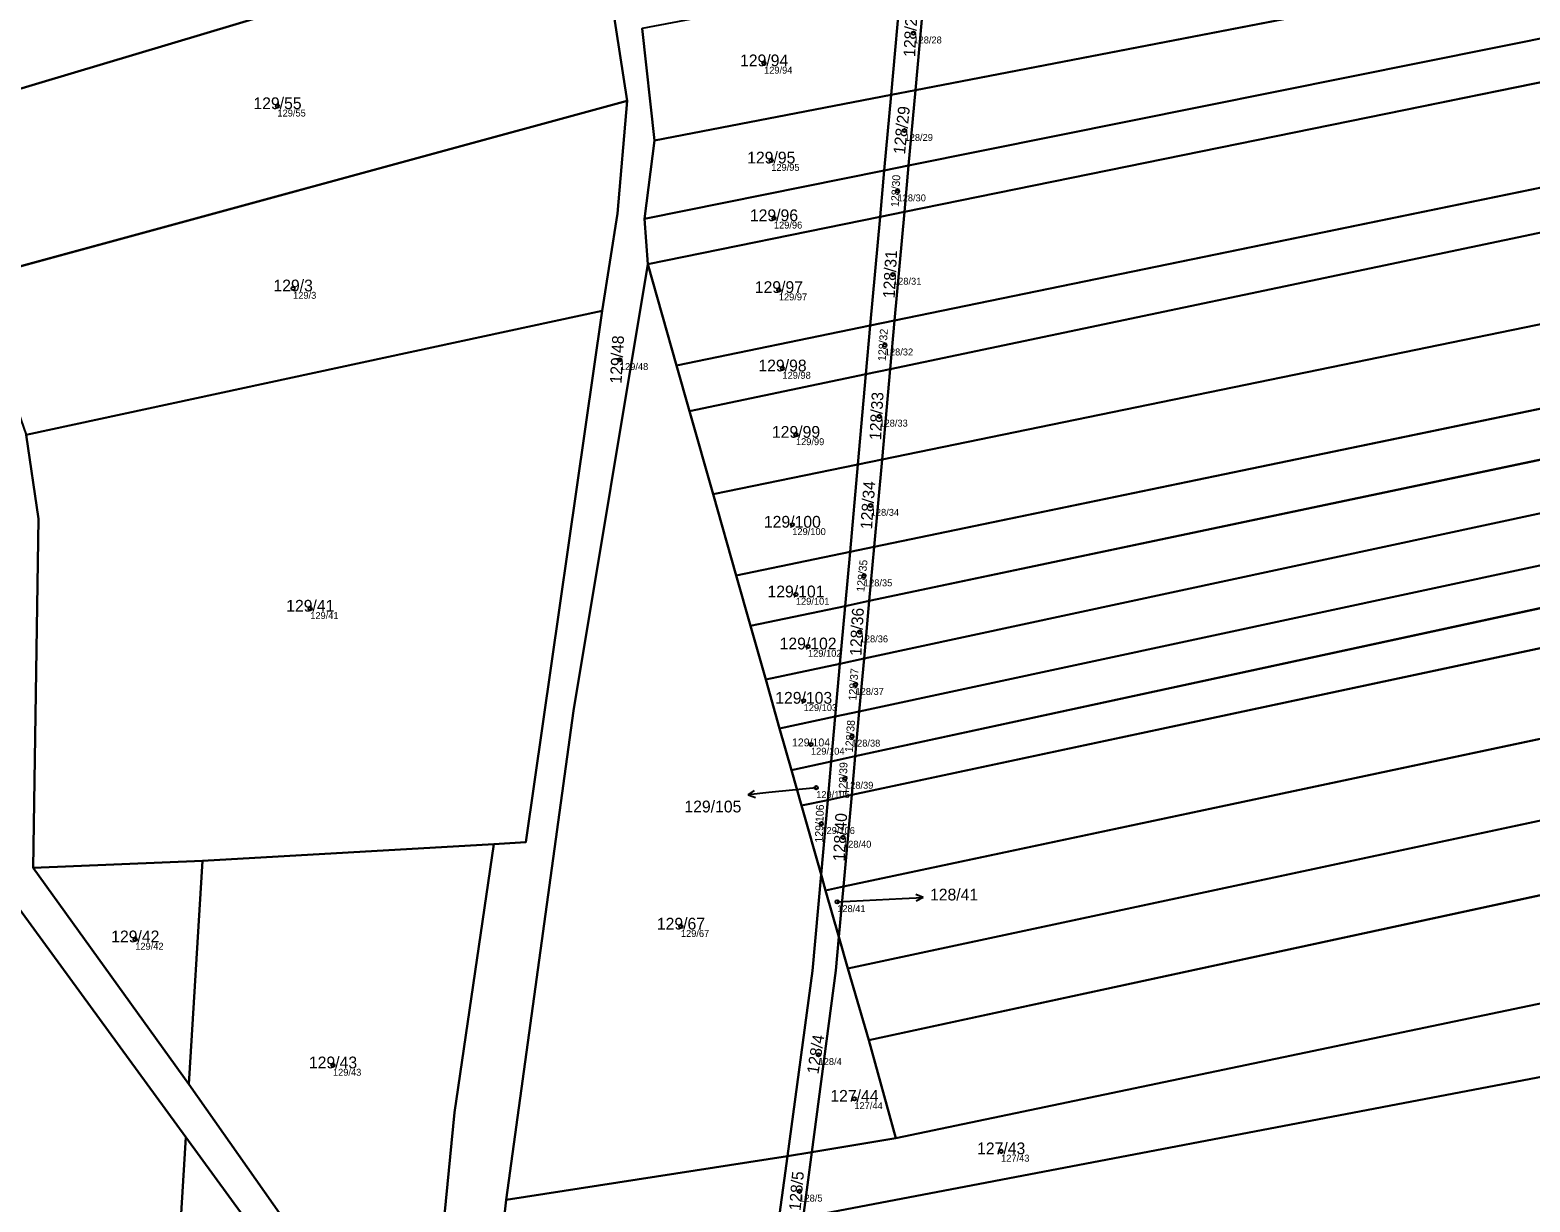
# Model space of a CAD drawing. Extents: x -603967 to -594699, y -1179315 to -1165625.
# Drawn here: x -597898.4 to -597682, y -1173367 to -1173197.8 of the extents above; entities that cross this region are included whole.
import ezdxf

# ---------------------------------------------------------------- set-up
doc = ezdxf.new("R2010")
doc.units = 0
for name, color, linetype in [('Definiční body', 7, 'Continuous'), ('Hranice parcel', 7, 'Continuous'), ('Parcelní čísla', 7, 'Continuous'), ('Polygon parcely', 7, 'Continuous'), ('Pop  PČ popisy', 7, 'Continuous')]:
    doc.layers.add(name, color=color, linetype=linetype)

msp = doc.modelspace()

# ---------------------------------------------------------------- linework, layer by layer
at = {"layer": 'Definiční body'}
for centre in [(-597770.92, -1173198.27994), (-597792.47, -1173202.63994), (-597862.68, -1173208.82994), (-597772.2, -1173212.34994), (-597791.44, -1173216.66994), (-597773.21, -1173221.07994), (-597791.05, -1173224.99994), (-597773.87, -1173233.10994), (-597860.42, -1173235.13994), (-597790.34, -1173235.36994), (-597775.05, -1173243.31994), (-597813.27, -1173245.42994), (-597789.82, -1173246.68994), (-597775.83, -1173253.58994), (-597787.87, -1173256.26994), (-597777.08, -1173266.46994), (-597788.4, -1173269.24994), (-597778.06, -1173276.64994), (-597787.88, -1173279.30994), (-597857.95, -1173281.36994), (-597778.67, -1173284.73994), (-597786.13, -1173286.81994), (-597779.28, -1173292.32994), (-597786.76, -1173294.65994), (-597785.7, -1173300.95994), (-597779.79, -1173299.78994), (-597784.95, -1173307.20994), (-597780.79, -1173305.86994), (-597784.2, -1173312.39994), (-597781.08, -1173314.37994), (-597781.92, -1173323.67994), (-597804.47, -1173327.25994), (-597883.2, -1173329.10994), (-597784.61, -1173345.75994), (-597854.67, -1173347.29994), (-597779.44, -1173352.11994), (-597758.27, -1173359.69994), (-597787.38, -1173365.46994)]:
    msp.add_circle(centre, 0.25, dxfattribs=at)
at = {"layer": 'Hranice parcel'}
for p, q in [((-597770.63, -1173206.5), (-597579.29, -1173169.58)), ((-597771.62, -1173217.4), (-597581.1, -1173179.02)), ((-597916.3, -1173211.25), (-597816.35, -1173181.29)), ((-597816.35, -1173181.29), (-597812.23, -1173208.04)), ((-597772.22, -1173224.08), (-597582.31, -1173185.32)), ((-597772.65, -1173190.5), (-597774.15, -1173207.18)), ((-597769.12, -1173189.83), (-597770.63, -1173206.5)), ((-597808.28, -1173213.76), (-597810.05, -1173197.62)), ((-597773.64, -1173239.78), (-597585.85, -1173201.13)), ((-597812.23, -1173208.04), (-597906.75, -1173233.85)), ((-597808.28, -1173213.76), (-597774.15, -1173207.18)), ((-597774.15, -1173207.18), (-597775.13, -1173218.11)), ((-597774.27, -1173246.79), (-597587.4, -1173207.52)), ((-597774.15, -1173207.18), (-597770.63, -1173206.5)), ((-597770.63, -1173206.5), (-597771.62, -1173217.4)), ((-597809.7, -1173225.08), (-597808.28, -1173213.76)), ((-597775.45, -1173259.82), (-597560.35, -1173215.6)), ((-597809.7, -1173225.08), (-597775.13, -1173218.11)), ((-597775.13, -1173218.11), (-597775.73, -1173224.8)), ((-597775.13, -1173218.11), (-597771.62, -1173217.4)), ((-597771.62, -1173217.4), (-597772.22, -1173224.08)), ((-597809.24, -1173231.64), (-597809.7, -1173225.08)), ((-597809.24, -1173231.64), (-597775.73, -1173224.8)), ((-597775.73, -1173224.8), (-597777.14, -1173240.5)), ((-597775.73, -1173224.8), (-597772.22, -1173224.08)), ((-597772.22, -1173224.08), (-597773.64, -1173239.78)), ((-597776.59, -1173272.46), (-597564.2, -1173228.37)), ((-597805.1, -1173246.25), (-597809.24, -1173231.64)), ((-597777.3, -1173280.25), (-597566.44, -1173235.83)), ((-597898.92, -1173256.25), (-597815.82, -1173238.39)), ((-597805.1, -1173246.25), (-597777.14, -1173240.5)), ((-597777.14, -1173240.5), (-597777.77, -1173247.52)), ((-597777.14, -1173240.5), (-597773.64, -1173239.78)), ((-597773.64, -1173239.78), (-597774.27, -1173246.79)), ((-597778.05, -1173288.56), (-597567.95, -1173243.42)), ((-597803.22, -1173252.87), (-597805.1, -1173246.25)), ((-597777.77, -1173247.52), (-597774.27, -1173246.79)), ((-597774.27, -1173246.79), (-597775.45, -1173259.82)), ((-597803.22, -1173252.87), (-597777.77, -1173247.52)), ((-597777.77, -1173247.52), (-597778.94, -1173260.54)), ((-597778.74, -1173296.2), (-597567.76, -1173250.91)), ((-597799.83, -1173264.83), (-597803.22, -1173252.87)), ((-597779.33, -1173302.68), (-597567.61, -1173256.87)), ((-597778.94, -1173260.54), (-597775.45, -1173259.82)), ((-597775.45, -1173259.82), (-597776.59, -1173272.46)), ((-597799.83, -1173264.83), (-597778.94, -1173260.54)), ((-597778.94, -1173260.54), (-597780.07, -1173273.18)), ((-597779.83, -1173308.25), (-597569.75, -1173263.44)), ((-597796.49, -1173276.59), (-597799.83, -1173264.83)), ((-597780.07, -1173273.18), (-597776.59, -1173272.46)), ((-597776.59, -1173272.46), (-597777.3, -1173280.25)), ((-597796.49, -1173276.59), (-597780.07, -1173273.18)), ((-597780.07, -1173273.18), (-597780.77, -1173280.98)), ((-597794.43, -1173283.86), (-597796.49, -1173276.59)), ((-597781.03, -1173321.48), (-597574.37, -1173277.63)), ((-597794.43, -1173283.86), (-597780.77, -1173280.98)), ((-597780.77, -1173280.98), (-597781.52, -1173289.31)), ((-597780.77, -1173280.98), (-597777.3, -1173280.25)), ((-597777.3, -1173280.25), (-597778.05, -1173288.56)), ((-597792.23, -1173291.61), (-597794.43, -1173283.86)), ((-597792.23, -1173291.61), (-597781.52, -1173289.31)), ((-597781.52, -1173289.31), (-597782.21, -1173296.94)), ((-597781.52, -1173289.31), (-597778.05, -1173288.56)), ((-597778.05, -1173288.56), (-597778.74, -1173296.2)), ((-597790.23, -1173298.66), (-597792.23, -1173291.61)), ((-597780.39, -1173333.33), (-597580.04, -1173290.5)), ((-597782.21, -1173296.94), (-597778.74, -1173296.2)), ((-597778.74, -1173296.2), (-597779.33, -1173302.68)), ((-597790.23, -1173298.66), (-597782.21, -1173296.94)), ((-597788.52, -1173304.67), (-597790.23, -1173298.66)), ((-597782.21, -1173296.94), (-597782.79, -1173303.43)), ((-597782.79, -1173303.43), (-597779.33, -1173302.68)), ((-597779.33, -1173302.68), (-597779.83, -1173308.25)), ((-597777.35, -1173343.67), (-597583.89, -1173301.84)), ((-597788.52, -1173304.67), (-597782.79, -1173303.43)), ((-597787.07, -1173309.8), (-597788.52, -1173304.67)), ((-597782.79, -1173303.43), (-597783.29, -1173308.99)), ((-597787.07, -1173309.8), (-597783.29, -1173308.99)), ((-597784.25, -1173319.72), (-597787.07, -1173309.8)), ((-597783.29, -1173308.99), (-597784.25, -1173319.72)), ((-597783.29, -1173308.99), (-597779.83, -1173308.25)), ((-597779.83, -1173308.25), (-597781.03, -1173321.48)), ((-597873.51, -1173317.76), (-597831.46, -1173315.35)), ((-597897.92, -1173318.78), (-597873.51, -1173317.76)), ((-597875.45, -1173349.99), (-597873.51, -1173317.76)), ((-597875.45, -1173349.99), (-597897.92, -1173318.78)), ((-597783.6, -1173322.03), (-597784.25, -1173319.72)), ((-597783.6, -1173322.03), (-597781.03, -1173321.48)), ((-597781.69, -1173328.74), (-597783.6, -1173322.03)), ((-597781.03, -1173321.48), (-597781.69, -1173328.74)), ((-597875.91, -1173357.65), (-597900.79, -1173323.49)), ((-597780.39, -1173333.33), (-597781.69, -1173328.74)), ((-597777.35, -1173343.67), (-597780.39, -1173333.33)), ((-597678.84, -1173338.04), (-597773.44, -1173357.81)), ((-597773.44, -1173357.81), (-597777.35, -1173343.67)), ((-597675.78, -1173348.07), (-597786.85, -1173369.25)), ((-597841.47, -1173398.41), (-597875.45, -1173349.99)), ((-597878.71, -1173404.2), (-597875.91, -1173357.65)), ((-597842.82, -1173403.09), (-597875.91, -1173357.65)), ((-597773.44, -1173357.81), (-597785.6, -1173359.83)), ((-597829.68, -1173366.71), (-597789.1, -1173360.41)), ((-597789.1, -1173360.41), (-597790.38, -1173369.9)), ((-597789.1, -1173360.41), (-597785.6, -1173359.83)), ((-597785.6, -1173359.83), (-597786.85, -1173369.25)), ((-597830.89, -1173377.41), (-597829.68, -1173366.71))]:
    msp.add_line(p, q, dxfattribs=at)
for points in [[(-597815.82, -1173238.39), (-597813.63, -1173224.32), (-597812.23, -1173208.04)], [(-597829.68, -1173366.71), (-597819.97, -1173296.09), (-597809.24, -1173231.64)], [(-597831.46, -1173315.35), (-597826.83, -1173315.09), (-597815.82, -1173238.39)], [(-597897.92, -1173318.78), (-597897.17, -1173268.39), (-597898.92, -1173256.25)], [(-597841.47, -1173398.41), (-597837.14, -1173354.1), (-597831.46, -1173315.35)], [(-597784.25, -1173319.72), (-597785.5, -1173333.66), (-597789.1, -1173360.41)], [(-597781.69, -1173328.74), (-597782.13, -1173333.58), (-597785.6, -1173359.83)]]:
    msp.add_lwpolyline(points, dxfattribs=at)
at = {"layer": 'Polygon parcely'}
for points in [[(-597868.05, -1172978.19), (-597856.03, -1173026.84), (-597831.11, -1173111.5), (-597822.95, -1173145.57), (-597822.21, -1173148.7), (-597816.35, -1173181.29), (-597812.23, -1173208.04), (-597813.63, -1173224.32), (-597815.82, -1173238.39), (-597826.83, -1173315.09), (-597831.46, -1173315.35), (-597837.14, -1173354.1), (-597841.47, -1173398.41)], [(-597830.89, -1173377.41), (-597829.68, -1173366.71), (-597819.97, -1173296.09), (-597809.24, -1173231.64), (-597809.7, -1173225.08), (-597808.28, -1173213.76), (-597810.05, -1173197.62)], [(-597841.47, -1173398.41), (-597875.45, -1173349.99), (-597897.92, -1173318.78), (-597897.17, -1173268.39), (-597898.92, -1173256.25)], [(-597900.79, -1173323.49), (-597875.91, -1173357.65), (-597842.82, -1173403.09)]]:
    msp.add_lwpolyline(points, dxfattribs=at)
for points in [[(-597816.35, -1173181.29), (-597822.21, -1173148.7), (-597922.8, -1173195.87), (-597916.3, -1173211.25)], [(-597578.94, -1173167.78), (-597576.49, -1173155.03), (-597576.38, -1173153.11), (-597769.12, -1173189.83), (-597770.63, -1173206.5), (-597579.29, -1173169.58)], [(-597581.1, -1173179.02), (-597579.29, -1173169.58), (-597770.63, -1173206.5), (-597771.62, -1173217.4)], [(-597582.31, -1173185.32), (-597581.1, -1173179.02), (-597771.62, -1173217.4), (-597772.22, -1173224.08)], [(-597906.75, -1173233.85), (-597812.23, -1173208.04), (-597816.35, -1173181.29), (-597916.3, -1173211.25)], [(-597772.22, -1173224.08), (-597773.64, -1173239.78), (-597585.85, -1173201.13), (-597583.42, -1173191.09), (-597582.31, -1173185.32)], [(-597774.15, -1173207.18), (-597772.65, -1173190.5), (-597810.05, -1173197.62), (-597808.28, -1173213.76)], [(-597770.63, -1173206.5), (-597769.12, -1173189.83), (-597772.65, -1173190.5), (-597774.15, -1173207.18)], [(-597773.64, -1173239.78), (-597774.27, -1173246.79), (-597587.4, -1173207.52), (-597585.85, -1173201.13)], [(-597558.84, -1173204.24), (-597587.4, -1173207.52), (-597774.27, -1173246.79), (-597775.45, -1173259.82), (-597560.35, -1173215.6)], [(-597898.92, -1173256.25), (-597815.82, -1173238.39), (-597813.63, -1173224.32), (-597812.23, -1173208.04), (-597906.75, -1173233.85)], [(-597775.13, -1173218.11), (-597774.15, -1173207.18), (-597808.28, -1173213.76), (-597809.7, -1173225.08)], [(-597774.15, -1173207.18), (-597775.13, -1173218.11), (-597771.62, -1173217.4), (-597770.63, -1173206.5)], [(-597564.2, -1173228.37), (-597560.35, -1173215.6), (-597775.45, -1173259.82), (-597776.59, -1173272.46)], [(-597775.73, -1173224.8), (-597775.13, -1173218.11), (-597809.7, -1173225.08), (-597809.24, -1173231.64)], [(-597772.22, -1173224.08), (-597771.62, -1173217.4), (-597775.13, -1173218.11), (-597775.73, -1173224.8)], [(-597777.14, -1173240.5), (-597775.73, -1173224.8), (-597809.24, -1173231.64), (-597805.1, -1173246.25)], [(-597773.64, -1173239.78), (-597772.22, -1173224.08), (-597775.73, -1173224.8), (-597777.14, -1173240.5)], [(-597566.44, -1173235.83), (-597564.2, -1173228.37), (-597776.59, -1173272.46), (-597777.3, -1173280.25)], [(-597788.52, -1173304.67), (-597790.23, -1173298.66), (-597792.23, -1173291.61), (-597794.43, -1173283.86), (-597796.49, -1173276.59), (-597799.83, -1173264.83), (-597803.22, -1173252.87), (-597805.1, -1173246.25), (-597809.24, -1173231.64), (-597819.97, -1173296.09), (-597829.68, -1173366.71), (-597789.1, -1173360.41), (-597785.5, -1173333.66), (-597784.25, -1173319.72), (-597787.07, -1173309.8)], [(-597777.3, -1173280.25), (-597778.05, -1173288.56), (-597567.95, -1173243.42), (-597568.01, -1173241.04), (-597566.44, -1173235.83)], [(-597873.51, -1173317.76), (-597831.46, -1173315.35), (-597826.83, -1173315.09), (-597815.82, -1173238.39), (-597898.92, -1173256.25), (-597897.17, -1173268.39), (-597897.92, -1173318.78)], [(-597777.77, -1173247.52), (-597777.14, -1173240.5), (-597805.1, -1173246.25), (-597803.22, -1173252.87)], [(-597774.27, -1173246.79), (-597773.64, -1173239.78), (-597777.14, -1173240.5), (-597777.77, -1173247.52)], [(-597567.76, -1173250.91), (-597567.95, -1173243.42), (-597778.05, -1173288.56), (-597778.74, -1173296.2)], [(-597777.77, -1173247.52), (-597778.94, -1173260.54), (-597775.45, -1173259.82), (-597774.27, -1173246.79)], [(-597778.94, -1173260.54), (-597777.77, -1173247.52), (-597803.22, -1173252.87), (-597799.83, -1173264.83)], [(-597567.61, -1173256.87), (-597567.76, -1173250.91), (-597778.74, -1173296.2), (-597779.33, -1173302.68)], [(-597569.75, -1173263.44), (-597567.61, -1173256.87), (-597779.33, -1173302.68), (-597779.83, -1173308.25)], [(-597778.94, -1173260.54), (-597780.07, -1173273.18), (-597776.59, -1173272.46), (-597775.45, -1173259.82)], [(-597780.07, -1173273.18), (-597778.94, -1173260.54), (-597799.83, -1173264.83), (-597796.49, -1173276.59)], [(-597574.37, -1173277.63), (-597569.75, -1173263.44), (-597779.83, -1173308.25), (-597781.03, -1173321.48)], [(-597780.07, -1173273.18), (-597780.77, -1173280.98), (-597777.3, -1173280.25), (-597776.59, -1173272.46)], [(-597780.77, -1173280.98), (-597780.07, -1173273.18), (-597796.49, -1173276.59), (-597794.43, -1173283.86)], [(-597781.03, -1173321.48), (-597781.69, -1173328.74), (-597780.39, -1173333.33), (-597580.04, -1173290.5), (-597574.37, -1173277.63)], [(-597781.52, -1173289.31), (-597780.77, -1173280.98), (-597794.43, -1173283.86), (-597792.23, -1173291.61)], [(-597778.05, -1173288.56), (-597777.3, -1173280.25), (-597780.77, -1173280.98), (-597781.52, -1173289.31)], [(-597782.21, -1173296.94), (-597781.52, -1173289.31), (-597792.23, -1173291.61), (-597790.23, -1173298.66)], [(-597781.52, -1173289.31), (-597782.21, -1173296.94), (-597778.74, -1173296.2), (-597778.05, -1173288.56)], [(-597582.13, -1173295.25), (-597580.04, -1173290.5), (-597780.39, -1173333.33), (-597777.35, -1173343.67), (-597583.89, -1173301.84)], [(-597782.21, -1173296.94), (-597782.79, -1173303.43), (-597779.33, -1173302.68), (-597778.74, -1173296.2)], [(-597782.79, -1173303.43), (-597782.21, -1173296.94), (-597790.23, -1173298.66), (-597788.52, -1173304.67)], [(-597782.79, -1173303.43), (-597783.29, -1173308.99), (-597779.83, -1173308.25), (-597779.33, -1173302.68)], [(-597586.65, -1173313.22), (-597583.89, -1173301.84), (-597777.35, -1173343.67), (-597773.44, -1173357.81), (-597678.84, -1173338.04), (-597635.59, -1173325.58)], [(-597783.29, -1173308.99), (-597782.79, -1173303.43), (-597788.52, -1173304.67), (-597787.07, -1173309.8)], [(-597784.25, -1173319.72), (-597783.29, -1173308.99), (-597787.07, -1173309.8)], [(-597781.03, -1173321.48), (-597779.83, -1173308.25), (-597783.29, -1173308.99), (-597784.25, -1173319.72), (-597783.6, -1173322.03)], [(-597841.47, -1173398.41), (-597837.14, -1173354.1), (-597831.46, -1173315.35), (-597873.51, -1173317.76), (-597875.45, -1173349.99)], [(-597875.45, -1173349.99), (-597873.51, -1173317.76), (-597897.92, -1173318.78)], [(-597783.6, -1173322.03), (-597784.25, -1173319.72), (-597785.5, -1173333.66), (-597789.1, -1173360.41), (-597785.6, -1173359.83), (-597782.13, -1173333.58), (-597781.69, -1173328.74)], [(-597781.69, -1173328.74), (-597781.03, -1173321.48), (-597783.6, -1173322.03)], [(-597875.91, -1173357.65), (-597900.79, -1173323.49), (-597902.1, -1173345.75), (-597903.25, -1173365.22), (-597904.55, -1173387.18), (-597905.42, -1173401.9), (-597878.71, -1173404.2)], [(-597777.35, -1173343.67), (-597780.39, -1173333.33), (-597781.69, -1173328.74), (-597782.13, -1173333.58), (-597785.6, -1173359.83), (-597773.44, -1173357.81)], [(-597773.44, -1173357.81), (-597785.6, -1173359.83), (-597786.85, -1173369.25), (-597675.78, -1173348.07), (-597678.84, -1173338.04)], [(-597786.85, -1173369.25), (-597790.14, -1173394.16), (-597725, -1173384.03), (-597669.23, -1173373.84), (-597669.95, -1173370.77), (-597672.91, -1173359.11), (-597674.55, -1173352.06), (-597675.78, -1173348.07)], [(-597842.82, -1173403.09), (-597875.91, -1173357.65), (-597878.71, -1173404.2), (-597843.78, -1173407.2)], [(-597790.38, -1173369.9), (-597789.1, -1173360.41), (-597829.68, -1173366.71), (-597830.89, -1173377.41)], [(-597786.85, -1173369.25), (-597785.6, -1173359.83), (-597789.1, -1173360.41), (-597790.38, -1173369.9)]]:
    msp.add_lwpolyline(points, close=True, dxfattribs=at)
at = {"layer": 'Pop  PČ popisy'}
for p, q in [((-597794.775, -1173308.224), (-597793.831, -1173307.621)), ((-597784.95, -1173307.21), (-597791.79, -1173307.91)), ((-597791.79, -1173307.91), (-597794.775, -1173308.224)), ((-597794.775, -1173308.224), (-597793.726, -1173308.617)), ((-597769.533, -1173323.053), (-597770.559, -1173322.605)), ((-597781.92, -1173323.68), (-597772.53, -1173323.21)), ((-597772.53, -1173323.21), (-597769.533, -1173323.053)), ((-597769.533, -1173323.053), (-597770.507, -1173323.605))]:
    msp.add_line(p, q, dxfattribs=at)

# ---------------------------------------------------------------- texts
at = {"layer": 'Definiční body'}
for s, p in [('128/28', (-597770.92, -1173199.769)), ('129/94', (-597792.47, -1173204.129)), ('129/55', (-597862.68, -1173210.319)), ('128/29', (-597772.2, -1173213.839)), ('129/95', (-597791.44, -1173218.159)), ('128/30', (-597773.21, -1173222.569)), ('129/96', (-597791.05, -1173226.489)), ('128/31', (-597773.87, -1173234.599)), ('129/3', (-597860.42, -1173236.629)), ('129/97', (-597790.34, -1173236.859)), ('128/32', (-597775.05, -1173244.809)), ('129/48', (-597813.27, -1173246.919)), ('129/98', (-597789.82, -1173248.179)), ('128/33', (-597775.83, -1173255.079)), ('129/99', (-597787.87, -1173257.759)), ('128/34', (-597777.08, -1173267.959)), ('129/100', (-597788.4, -1173270.739)), ('128/35', (-597778.06, -1173278.139)), ('129/101', (-597787.88, -1173280.799)), ('129/41', (-597857.95, -1173282.859)), ('128/36', (-597778.67, -1173286.229)), ('129/102', (-597786.13, -1173288.309)), ('128/37', (-597779.28, -1173293.819)), ('129/103', (-597786.76, -1173296.149)), ('128/38', (-597779.79, -1173301.279)), ('129/104', (-597785.7, -1173302.449)), ('129/105', (-597784.95, -1173308.699)), ('128/39', (-597780.79, -1173307.359)), ('129/106', (-597784.2, -1173313.889)), ('128/40', (-597781.08, -1173315.869)), ('128/41', (-597781.92, -1173325.169)), ('129/67', (-597804.47, -1173328.749)), ('129/42', (-597883.2, -1173330.599)), ('128/4', (-597784.61, -1173347.249)), ('129/43', (-597854.67, -1173348.789)), ('127/44', (-597779.44, -1173353.609)), ('127/43', (-597758.27, -1173361.189)), ('128/5', (-597787.38, -1173366.959))]:
    msp.add_text(s, height=0.999996, dxfattribs=at).set_placement(p)
at = {"layer": 'Parcelní čísla'}
for s, height, rotation, p in [('128/28', 1.699998, 87, (-597770.677, -1173201.763)), ('128/29', 1.699998, 84, (-597772.139, -1173215.841)), ('128/30', 1.14, 87, (-597773.047, -1173223.416)), ('128/31', 1.699998, 87, (-597773.627, -1173236.593)), ('129/48', 1.699998, 87, (-597813.027, -1173248.913)), ('128/32', 1.14, 86, (-597774.927, -1173245.658)), ('128/33', 1.699998, 87, (-597775.587, -1173257.073)), ('128/34', 1.699998, 86, (-597776.897, -1173269.957)), ('128/35', 1.14, 84, (-597778.019, -1173278.991)), ('128/36', 1.699998, 87, (-597778.427, -1173288.223)), ('128/37', 1.14, 86, (-597779.157, -1173294.668)), ('128/38', 1.14, 86, (-597779.667, -1173302.128)), ('128/39', 1.14, 87.9999972, (-597780.586, -1173308.203)), ('129/106', 1.14, 87.9999972, (-597784.011, -1173315.155)), ('128/40', 1.699998, 87, (-597780.837, -1173317.863)), ('128/4', 1.699998, 81, (-597784.633, -1173348.627)), ('128/5', 1.699998, 85, (-597787.203, -1173368.332))]:
    msp.add_text(s, height=height, rotation=rotation, dxfattribs=at).set_placement(p)
for s, height, p in [('129/94', 1.699998, (-597795.936, -1173203.065)), ('129/55', 1.699998, (-597866.146, -1173209.255)), ('129/95', 1.699998, (-597794.906, -1173217.095)), ('129/96', 1.699998, (-597794.516, -1173225.425)), ('129/3', 1.699998, (-597863.256, -1173235.565)), ('129/97', 1.699998, (-597793.806, -1173235.795)), ('129/98', 1.699998, (-597793.286, -1173247.115)), ('129/99', 1.699998, (-597791.336, -1173256.695)), ('129/100', 1.699998, (-597792.496, -1173269.675)), ('129/101', 1.699998, (-597791.976, -1173279.735)), ('129/41', 1.699998, (-597861.416, -1173281.795)), ('129/102', 1.699998, (-597790.226, -1173287.245)), ('129/103', 1.699998, (-597790.856, -1173295.085)), ('129/104', 1.14, (-597788.447, -1173301.245)), ('129/105', 1.699998, (-597803.963, -1173310.775)), ('128/41', 1.699998, (-597768.53, -1173323.485)), ('129/67', 1.699998, (-597807.936, -1173327.685)), ('129/42', 1.699998, (-597886.666, -1173329.535)), ('129/43', 1.699998, (-597858.136, -1173347.725)), ('127/44', 1.699998, (-597782.906, -1173352.545)), ('127/43', 1.699998, (-597761.736, -1173360.125))]:
    msp.add_text(s, height=height, dxfattribs=at).set_placement(p)

doc.saveas('drawing.dxf')
